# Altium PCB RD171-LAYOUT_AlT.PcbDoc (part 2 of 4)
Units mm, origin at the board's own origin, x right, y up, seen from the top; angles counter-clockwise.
Board outline 318.5 x 127 mm, 6 copper layers (TOP, Mid-Layer 1, Mid-Layer 2, Mid-Layer 3, Mid-Layer 4, BOTTOM), stack 1.422 mm thick; 473 components, 225 nets, 1188 pads, 1192 vias.
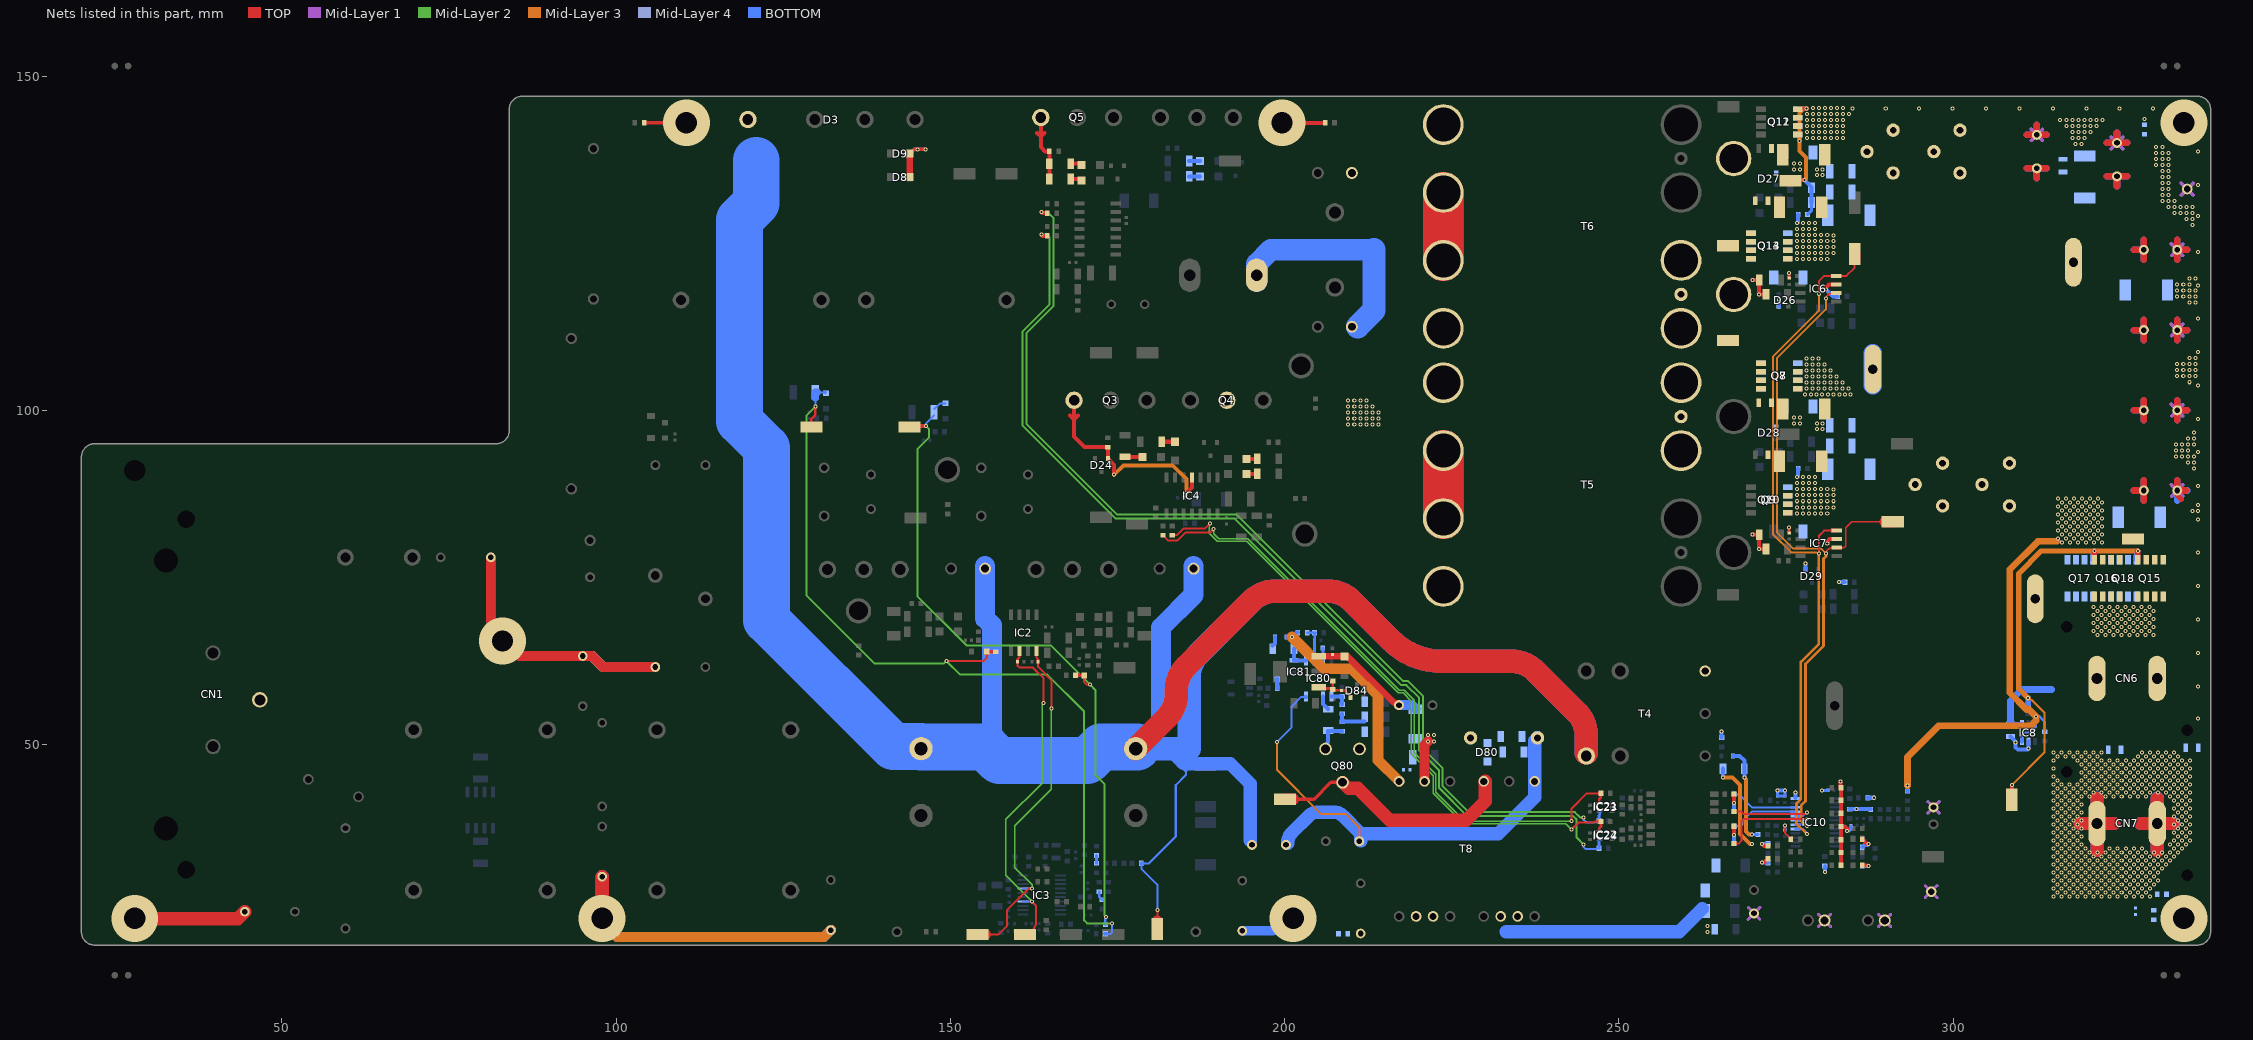
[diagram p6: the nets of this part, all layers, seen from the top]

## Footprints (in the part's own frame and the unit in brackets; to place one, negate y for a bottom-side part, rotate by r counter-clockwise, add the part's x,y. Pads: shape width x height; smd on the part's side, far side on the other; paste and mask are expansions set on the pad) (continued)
T_I_AN0545_GS [mm] "KC00080BKP"
  round 6.1 hole 5.1 paste-6.2 mask+0: 1(-17.78,15.24) 3(-17.78,5.08) 4(-17.78,-5.08) 6(-17.78,-15.24) 7(17.78,-15.24) 9(17.78,-5.08) 10(17.78,5.08) 12(17.78,15.24)
  round 2 hole 1 paste-2.1 mask+0: 8(17.78,-10.16) 11(17.78,10.16)
  round 5.3 hole 4.3 paste-5.4 mask+0: 13(25.65,-10.16) 14(25.65,10.16)
  silkscreen extent -19.5,-17.5 19.5,17.5
T_I_P009-203_PO [mm] "KC00080BKP"
  round 1.6 hole 1 paste-1.7 mask+0: 1(-3.6,-3.5) 2(3.6,-3.5)
  round 1.5 hole 0.9 paste-1.6 mask+0: 3(2.575,3.5) 4(-2.575,3.5)
  silkscreen extent -6,-5.2 6,6.8
T_I_PE-63587NL_PU [mm] "KC00080BKP"
  round 2.6 hole 1.6 paste-2.7 mask+0: 1(-8.89,6.35) 2(-8.89,-6.35) 6(-3.81,6.35) 7(-3.81,-6.35)
  round 1.7 hole 1.1 paste-1.8 mask+0: 3(8.89,6.35) 4(8.89,0) 5(8.89,-6.35)
  silkscreen extent -11.43,-8.89 11.43,8.89
T_I_WT2020_GS [mm] "KC00080BKP"
  round 1.6 hole 1.05 paste-1.7 mask+0: 1(-10.1,10.14) 2(-10.1,6.33) 3(-10.1,2.52) 4(-10.1,-2.52) 5(-10.1,-6.33) 6(-10.1,-10.14) 7(10.1,-10.14) 8(10.1,-7.6) 9(10.1,-5.06) 10(10.1,-2.52) 11(10.1,2.52) 12(10.1,5.06) 13(10.1,7.6) 14(10.1,10.14)
  silkscreen extent -11.6,-11.6 11.6,11.6
TM_I_AC-P05CP24_ED [mm] "KC00080BKP"
  round 2.3 hole 1.65 paste-2.4 mask+0: 1(6.2,-15.8) 2(-0.8,-22.8) 3(-7.8,-15.8)
  round 0 hole 2.6 slot 5.8 at 90 deg unplated paste-5.8 mask+0: ""(-26.2,-11.8) ""(26.2,-11.8)
  round 0 hole 3.6 unplated paste-3.6 mask+0: ""(-20.05,-8.75) ""(20.05,-8.75)
  silkscreen extent -27.5,-23.8 27.5,2.9
TM_I_OP-910_GS [mm] "KC00080BKP"
  oval 6.8x2.6 / inner round 0 / far side oval 6.8x2.6 hole 1.6 slot 5.8 at 0 deg paste-7 mask+0: 1(0,4.5) 2(0,-4.5)
  round 0 hole 1.7 unplated paste-1.7 mask+0: ""(-7.75,-9) ""(7.75,9)
  silkscreen extent -9.5,-10.5 9.5,10.5
TP_I_LC-22_GS [mm] "KC00080BKP"
  round 1.6 hole 1 paste-1.7 mask+0: 1(0,0)
  silkscreen extent -1.65,-1.65 1.65,1.65
TP_I_TH2.8_TBLC3.8_ILC0_RC3.9_GS [mm] "KC00080BKP"
  round 3.8 / inner round 0 / far side round 3.8 hole 2.8 paste-3.9 mask+0: 1(0,0)
  silkscreen extent -2.15,-2.15 2.12,2.15
TP_S_HK-2_M8 [mm] "KC00080BKP"
  rect 3.3x1.7 smd paste-3.4 mask+0: 1(0,0)
  silkscreen extent -2,-1.2 2,1.2
TR_I_TO220SIS_TS_1 [mm] "KC00080BKP"
  round 1.9 hole 1.3 paste-2 mask+0: D(0,-5) G(-2.54,0) S(2.54,0)
  silkscreen extent -5,-3.84 5,2.92
TR_I_TO247_3_TS [mm] "KC00080BKP"
  round 2.6 hole 1.6 paste-2.7 mask+0: D(0,0) G(-5.44,0) S(5.44,0)
  silkscreen extent -7.97,-2.29 7.97,2.73
TR_S_SOP-ADVANCE_TS#1 [mm] "KC00080BKP"
  rect 0.85x1.45 smd paste-1.55 mask+0: 1(-1.905,-2.75) 2(-0.635,-2.75) 3(0.635,-2.75) 4(1.905,-2.75) 5(1.905,2.75) 6(0.635,2.75) 7(-0.635,2.75) 8(-1.905,2.75)
  silkscreen extent -2.58,-2.5 2.57,2.5
TR_S_SOP-ADVANCE_TS#2 [mm] "KC00080BKP"
  rect 0.85x1.45 smd paste-1.55 mask+0: 1(1.905,2.75) 2(0.635,2.75) 3(-0.635,2.75) 4(-1.905,2.75) 5(-1.905,-2.75) 6(-0.635,-2.75) 7(0.635,-2.75) 8(1.905,-2.75)
  silkscreen extent -2.58,-2.5 2.57,2.5
ZD_I_TND14V-561_CC [mm] "KC00080BKP"
  round 1.6 hole 1.05 paste-1.7 mask+0: 1(3.75,-1.3) 2(-3.75,1.3)
  silkscreen extent -8,-3.35 8,3.35

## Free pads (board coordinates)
  round 0 hole 3.2 unplated paste-3.2 mask+0: ""(28,91)
  round 0 hole 2 unplated paste-2 mask+0: ""(32.25,15.5) ""(32.25,151.5) ""(326.25,15.5) ""(326.25,151.5)

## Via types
v1: diameter 0.6, hole 0.3, TOP to BOTTOM, 1184 vias
v2: diameter 7, hole 3.2, TOP to BOTTOM, 8 vias

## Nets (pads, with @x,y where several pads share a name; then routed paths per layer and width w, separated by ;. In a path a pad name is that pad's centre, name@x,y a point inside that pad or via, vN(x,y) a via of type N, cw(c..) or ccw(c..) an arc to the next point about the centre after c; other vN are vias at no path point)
$BN000001: R90.2 R227.1 | length 1.2
  BOTTOM w0.4: R227.1@171.85,32.25 R90.2@171.85,33.4
$BN000002: R2.2 R228.1 | length 1.4
  BOTTOM w0.4: R228.1@172.25,28 172.25,27.25 R2.2@172.7,26.8
ADJ: C805.1 D84.A IC81.ADJ R810.2 R811.1 | length 6.9
  TOP w0.4: IC81.ADJ@205.1,58.6 205.3,58.4 207,58.4 R811.1@207.2,58.2 ; R810.2@207.2,59.5 R811.1@207.2,58.2 ; C805.1@208.5,58.125 207.275,58.125 R811.1@207.2,58.2 ; C805.1@208.5,58.15 208.5,58.1 209.05,58.1 209.85,57.3 D84.A@209.85,57.05
AUX: C810.2 D81.A R808.2 T8.6 | length 32.6
  Mid-Layer 3 w1.6: v1(201.1,66.1) 205.85,61.35 210,61.35 213.95,57.4 213.95,47.66 T8.6@217.11,44.5
  BOTTOM w0.6: D81.A@200.25,66.1 v1(201.1,66.1) 201.75,66.75 R808.2@201.95,66.75
CONN002: C19.1 D24.A IC4.11 Q3.S Q4.D R31.1 T5.1 T6.1 | length 35.1
  TOP w0.6: 167.9,99.2 168.5,98.6 ; Q3.S@168.5,101.5 168.5,98.6 ; 169.1,99.2 168.5,98.6 ; v1(174.5,90.4) 174.5,91.85 D24.A@173.55,92.8 R31.1@173.55,94.5 170.05,94.5 168.5,96.05 168.5,98.6 ; v1(185.3,87.65) 186.1,88.45 IC4.11@186.1,89.9
  Mid-Layer 3 w0.6: v1(174.5,90.4) 175.85,91.75 183.25,91.75 185.3,89.7 v1(185.3,87.65)
  BOTTOM w0.45: C19.1@184.925,86.9 185.3,87.275 v1(185.3,87.65)
CONN003: D18.C D19.A L3.2 T5.6 T6.6 | length 33.7
  BOTTOM w3.2: L3.2@195.8,119.3 L3.2@195.8,120.2 195.8,121.9 197.9,124 213.35,124
  BOTTOM w3.5: D19.A@210.9,112.5 213.35,114.95 213.35,124 213.25,123.9
  other v1: 209.5,97.9 210.4,97.9 211.3,97.9 212.2,97.9 213.1,97.9 214,97.9 209.5,98.8 210.4,98.8 211.3,98.8 212.2,98.8 213.1,98.8 214,98.8 209.5,99.7 210.4,99.7 211.3,99.7 212.2,99.7 213.1,99.7 214,99.7 209.5,100.6 210.4,100.6 211.3,100.6 212.2,100.6 213.1,100.6 209.5,101.5 210.4,101.5 211.3,101.5 212.2,101.5
CONN004: C2.2 C3.2 C4.2 C5.2 C8.2 C9.2 C59.2 C102.2 IC8.3 IC8.6 L5.2 L6.2 Q15.1 Q15.2 Q15.3 Q16.1 Q16.2 Q16.3 Q17.1 Q17.2 Q17.3 Q18.1 Q18.2 Q18.3 R75.2 R77.1 R78.1 R106.1 R107.2 R128.2 R129.1 R199.2 R200.2 R201.2 TP31.1 | length 123.1
  TOP w1: 311,136.2 C8.2@312.5,136.2 ; 312.5,134.7 C8.2@312.5,136.2 ; 314,136.2 C8.2@312.5,136.2 ; 323,135 C9.2@324.5,135 ; 324.5,133.5 C9.2@324.5,135 ; 326,135 C9.2@324.5,135 ; 327,88 C5.2@328.5,88 ; 327,100 C4.2@328.5,100 ; 327,112 C3.2@328.5,112 ; 327,124 C2.2@328.5,124 ; 328.5,86.5 C5.2@328.5,88 ; 328.5,89.5 C5.2@328.5,88 ; 328.5,98.5 C4.2@328.5,100 ; 328.5,101.5 C4.2@328.5,100 ; 328.5,110.5 C3.2@328.5,112 ; 328.5,113.5 C3.2@328.5,112 ; 328.5,122.5 C2.2@328.5,124 ; 328.5,125.5 C2.2@328.5,124
  Mid-Layer 1 w0.3: v1(315.65,80.8) v1(316.25,80.2)
  Mid-Layer 3 w1: v1(293.15,43.85) 293.15,48.15 297.8,52.8 311.6,52.8 312.4,53.6 v1(312.4,54.2) 311.35,55.25 310.95,55.25 308.45,57.75 308.45,76.2 312.65,80.4 315.52,80.4
  BOTTOM w0.3: IC8.3@310.3,50.95 310.3,51.4 310.7,51.8 311.8,51.8 312.2,52.2 IC8.6@312.2,52.85
  BOTTOM w0.4: v1(312.4,54.2) 312.9,54.2 313.7,53.4 C59.2@313.7,51.9
  BOTTOM w0.6: R75.2@293.15,43 v1(293.15,43.85) ; IC8.3@310.3,50.5 IC8.3@310.3,50.95 ; IC8.6@312.2,52.85 IC8.6@312.2,53.1 312.2,53.75 312.4,53.95 v1(312.4,54.2)
  BOTTOM w1: 311,136.2 C8.2@312.5,136.2 ; 312.5,134.7 C8.2@312.5,136.2 ; 314,136.2 C8.2@312.5,136.2 ; 323,135 C9.2@324.5,135 ; 324.5,133.5 C9.2@324.5,135 ; 326,135 C9.2@324.5,135 ; 327,88 C5.2@328.5,88 ; 327,100 C4.2@328.5,100 ; 327,112 C3.2@328.5,112 ; 327,124 C2.2@328.5,124 ; 328.5,86.5 C5.2@328.5,88 ; 328.5,89.5 C5.2@328.5,88 ; 328.5,98.5 C4.2@328.5,100 ; 328.5,101.5 C4.2@328.5,100 ; 328.5,110.5 C3.2@328.5,112 ; 328.5,113.5 C3.2@328.5,112 ; 328.5,122.5 C2.2@328.5,124 ; 328.5,125.5 C2.2@328.5,124
  other v1: 317.45,80.2 318.65,80.2 319.85,80.2 321.05,80.2 322.25,80.2 316.85,80.8 318.05,80.8 319.25,80.8 320.45,80.8 321.65,80.8 316.25,81.4 317.45,81.4 318.65,81.4 319.85,81.4 321.05,81.4 322.25,81.4 315.65,82 316.85,82 318.05,82 319.25,82 320.45,82 321.65,82 316.25,82.6 317.45,82.6 318.65,82.6 319.85,82.6 321.05,82.6 322.25,82.6 315.65,83.2 316.85,83.2 318.05,83.2 319.25,83.2 320.45,83.2 321.65,83.2 316.25,83.8 317.45,83.8 318.65,83.8 319.85,83.8 321.05,83.8 322.25,83.8 315.65,84.4 316.85,84.4 318.05,84.4 319.25,84.4 320.45,84.4 321.65,84.4 316.25,85 317.45,85 318.65,85 319.85,85 321.05,85 322.25,85 315.65,85.6 316.85,85.6 318.05,85.6 319.25,85.6 320.45,85.6 321.65,85.6 316.25,86.2 317.45,86.2 318.65,86.2 319.85,86.2 321.05,86.2 322.25,86.2 315.65,86.8 316.85,86.8 318.05,86.8 319.25,86.8 320.45,86.8 321.65,86.8
CS: D14.C R67.2 R185.2 | length 14.7
  Mid-Layer 3 w0.6: v1(268.75,45.05) 269,44.8 269,37 269.45,36.55 v1(269.9,36.55)
  BOTTOM w0.4: v1(269.9,36.55) R67.2@270.8,36.55
  BOTTOM w0.6: D14.C@267.05,48.3 268.05,48.3 268.75,47.6 R185.2@268.75,46.4 v1(268.75,45.05)
CSA: D13.C D33.C R7.2 R87.1 R170.1 TP2.1 | length 131.4
  TOP w0.3: v1(149.4,62.5) 155,62.5 155.45,62.95 D33.C@155.45,63.667
  TOP w0.4: TP2.1@129.2,97.5 129.2,98.7 129.8,99.3 v1(129.8,100.55)
  TOP w0.5: D33.C@155.4,63.9 R87.1@156.7,63.9
  TOP w0.8: D33.C@155.45,63.667 D33.C@155.45,63.9
  Mid-Layer 2 w0.3: v1(129.8,100.55) 128.45,99.2 128.45,72.333 138.683,62.1 149,62.1 v1(149.4,62.5) 151.45,60.45 164.499,60.45 170,54.949 170,23.7 170.45,23.25 v1(174.2,23.25)
  BOTTOM w0.3: v1(129.8,100.55) R7.2@129.8,101.867 ; R7.2@130.053,102.7 D13.C@131.136,102.7 ; R170.1@173.337,21.7 173.95,21.7 174.2,21.95 v1(174.2,23.25)
  BOTTOM w0.5: D13.C@131.136,102.7 D13.C@131.3,102.7
  BOTTOM w0.58: R170.1@173.14,21.7 R170.1@173.337,21.7
  BOTTOM w1.1: R7.2@129.8,101.867 R7.2@129.8,102.7 R7.2@130.053,102.7
CSB: D12.C D31.C R8.2 R83.1 R169.1 TP1.1 | length 103.6
  TOP w0.3: D31.C@170,60.35 170,59.35 170.35,59 v1(170.85,59)
  TOP w0.5: R83.1@168.7,60.35 D31.C@170,60.35
  TOP w0.6: TP1.1@144.7,97.65 v1(146.35,97.65)
  Mid-Layer 2 w0.3: v1(146.35,97.65) 146.8,97.2 146.8,95.95 145.05,94.2 145.05,72.2 152.4,64.85 165,64.85 v1(170.85,59) 171.7,58.15 171.7,45.449 173.05,44.099 173.05,24.45 v1(173.3,24.2)
  BOTTOM w0.3: v1(146.35,97.65) 146.35,98.05 R8.2@147.55,99.25 ; R8.2@147.6,100.2 148.45,101.05 D12.C@149.25,101.05
  BOTTOM w0.4: R169.1@173.175,23.075 173.175,23.85 v1(173.3,24.2)
FG1: CN1.2
FG2: C79.1 | length 13.4
  TOP w2: 31.5,23.95 43.4,23.95 C79.1@44.45,25
  other v2: 28,24
FG3: C32.1 C64.1 C78.1 | length 84.1
  TOP w1.45: v2@81.25,68.5 C78.1@81.25,78 ; v2@85.5,63.25 C32.1@95,63.25 96.375,63.25 ; 96.4,63.25 96.375,63.25 ; C64.1@105.85,61.6 98.025,61.6 96.375,63.25
  Mid-Layer 3 w1.45: C32.1@95,63.25 96.375,63.25 98.025,61.6 C64.1@105.85,61.6
  Mid-Layer 4 w1.45: C32.1@95,63.25 96.375,63.25 98.025,61.6 C64.1@105.85,61.6
  BOTTOM w1.45: v2@81.25,68.5 C78.1@81.25,78 ; v2@85.5,63.25 C32.1@95,63.25 96.375,63.25 ; 96.4,63.25 98.05,61.6 C64.1@105.85,61.6
  other v2: 83,65.5
FG4: C31.1 C63.1 | length 109.7
  TOP w2: v2(97.9,24) C31.1@97.9,30.25
  Mid-Layer 3 w1.5: 100.1,21.25 131.1,21.25 C63.1@132.1,22.25
  Mid-Layer 4 w1.5: 100.1,21.25 131.1,21.25 C63.1@132.1,22.25
  BOTTOM w1.5: 100.1,21.25 131.1,21.25 C63.1@132.1,22.25
  BOTTOM w2: v2(97.9,24) C31.1@97.9,30.25
FG5: C101.2 R805.2 | length 4.6
  BOTTOM w1.45: C101.2@193.65,22.15 198.25,22.15
  other v2: 201.25,24
FG6: C93.1 C94.2 R205.1 R206.1
  other v2: 334.5,24
FG7: R204.1
  other v2: 334.5,143
GDA: C81.2 IC2.2 IC3.14 TP5.1 | length 51.6
  TOP w0.3: C81.2@159.95,62.4 159.95,62.675 160.1,62.825 ; C81.2@160.025,62.225 160.025,61.825 160.35,61.5 162.35,61.5 163.95,59.9 v1(163.95,56.2) ; C81.2@160.025,62.4 160.1,62.4 160.1,62.825 ; IC2.2@160.315,64 160.315,63.04 160.1,62.825 ; TP5.1@162,21.6 162.8,23.123 162.8,25.925 v1(162.2,26.525)
  TOP w0.45: C81.2@160.025,62.225 C81.2@160.025,62.4
  Mid-Layer 2 w0.2: v1(162.2,26.525) 158.25,30.475 158.25,38.8 163.7,44.25 163.7,55.95 v1(163.95,56.2)
  BOTTOM w0.3: IC3.14@160.85,26.525 v1(162.2,26.525)
GDB: C80.2 IC2.4 IC3.17 TP6.1 | length 53.9
  TOP w0.3: TP6.1@155.233,21.6 157.2,21.6 158.45,22.85 158.45,25.2 161.75,28.5 v1(162.2,28.5) ; IC2.4@162.855,64 162.855,63.045 163.05,62.85 ; C80.2@163.125,62.225 163.125,61.625 165.1,59.65 v1(165.1,55.4) ; C80.2@163.125,62.4 163.05,62.4 163.05,62.85 ; C80.2@163.2,62.5 163.2,62.7 163.05,62.85
  TOP w0.45: C80.2@163.125,62.225 C80.2@163.125,62.4
  TOP w1.7: TP6.1@154.05,21.6 TP6.1@155.233,21.6
  Mid-Layer 2 w0.2: v1(162.2,28.5) 162.2,29.05 159.65,31.6 159.65,37.886 165.1,43.336 v1(165.1,55.4)
  BOTTOM w0.3: IC3.17@160.85,28.475 161.8,28.475 v1(162.2,28.5)
HS1_1: R224.2 | length 6.4
  TOP w0.6: v2(199.6,143) R224.2@206.05,143
HS1_2: R225.2 | length 6.3
  TOP w0.5: R225.2@104.2,143 v2(110.5,143)
IN: C804.2 C808.1 D82.C D83.C IC81.IN | length 17.9
  TOP w0.3: 207.15,63.2 C808.1@207.15,63.45
  TOP w0.95: IC81.IN@205.1,63.2 207.15,63.2 D83.C@208.95,63.2
  TOP w1: D83.C@208.9,63.2 209.4,63.2 216.236,56.364 C804.2@217.1,55.9
  BOTTOM w1.5: C804.2@217.1,55.9 219,55.9 D82.C@219.55,55.35
LGND: C2.1 C3.1 C4.1 C5.1 C8.1 C9.1 C23.1 C24.1 C25.1 C26.1 C27.1 C51.1 C60.1 C61.1 C68.1 C69.1 C88.1 C89.1 C90.1 C91.1 C92.1 C94.1 C99.1 C100.1 C102.1 C809.1 C811.1 CN7.1 CN7.2 CN8.2 CN9.2 CN10.2 D26.A D27.A D28.A D29.A IC6.3 IC7.3 IC8.2 IC10.24 Q7.1 Q7.2 Q7.3 Q8.1 Q8.2 Q8.3 Q9.1 Q9.2 Q9.3 Q10.1 Q10.2 Q10.3 Q11.1 Q11.2 Q11.3 Q12.1 Q12.2 Q12.3 Q13.1 Q13.2 Q13.3 Q14.1 Q14.2 Q14.3 R9.1 R19.1 R21.1 R22.1 R25.1 R43.1 R45.1 R48.1 R50.1 R51.1 R52.1 R53.1 R54.1 R55.1 R56.1 R61.1 R64.1 R66.1 R70.1 R76.1 R105.1 R118.1 R119.1 R140.1 R141.1 R180.1 R181.1 R182.1 R184.1 R185.1 R194.2 R195.2 R196.2 R197.2 R199.1 R200.1 R201.1 R204.2 R205.2 R206.2 R208.1 R209.1 R805.1 R820.1 T4.3 T8.8 T8.9 TP41.1 TP42.1 | length 306.5
  TOP w0.3: v1@274.8,37.95 v1(274.8,37.9) 274.8,36.81 R70.1@275.76,35.85
  TOP w0.45: C60.1@275.45,81.7 v1(275.45,82.45) ; C61.1@275.45,119.8 v1(275.45,120.55)
  TOP w0.6: v1(267.2,36.5) R197.2@267.2,37.8 ; v1(267.2,41.3) R196.2@267.2,42.6 ; v1(269.95,81.4) C91.1@270.95,81.4 ; v1(269.95,119.5) C88.1@270.95,119.5 ; C91.1@270.95,81.35 v1(270.95,79.25) C90.1@272,79.25 ; C88.1@270.95,119.45 v1(270.95,117.35) C89.1@272,117.35 ; v1(271.4,32.35) 271.7,32.35 R208.1@272.3,32.95 ; v1(271.4,35.15) 271.7,34.85 R209.1@272.25,34.85 ; v1(280.95,118.1) 280.95,118.385 281.4,118.835 IC6.3@282.5,118.835 ; v1(281.15,80.05) 281.15,80.4 281.485,80.735 IC7.3@282.5,80.735 ; R50.1@283.15,43.55 v1(283.15,44.5) ; R182.1@283.2,31.95 R53.1@283.2,33.85 R51.1@283.2,35.75 R180.1@283.2,37.7 ; R50.1@283.2,43.55 R181.1@283.2,41.65 R52.1@283.2,39.75 R180.1@283.2,37.75 R180.1@283.2,37.7 ; v1(284.1,37.05) 284.1,37.45 283.85,37.7 R180.1@283.2,37.7 ; R184.1@286.4,31.95 287.2,31.95 v1(287.3,31.85) ; R55.1@286.4,35.85 287.1,35.15 v1(287.35,35.15)
  TOP w0.8: C5.1@333.5,88 333.5,87.265 334.115,86.65
  TOP w1: 311,141.2 C8.1@312.5,141.2 ; 312.5,142.7 C8.1@312.5,141.2 ; 314,141.2 C8.1@312.5,141.2 ; 323,140 C9.1@324.5,140 ; 324.5,141.5 C9.1@324.5,140 ; 326,140 C9.1@324.5,140 ; 333.5,89.5 C5.1@333.5,88 334.85,88 ; 333.5,98.5 C4.1@333.5,100 ; 333.5,101.5 C4.1@333.5,100 ; 333.5,110.5 C3.1@333.5,112 ; 333.5,113.5 C3.1@333.5,112 ; 333.5,122.5 C2.1@333.5,124 ; 333.5,125.5 C2.1@333.5,124 ; 335,100 C4.1@333.5,100 ; 335,112 C3.1@333.5,112 ; 335,124 C2.1@333.5,124
  TOP w2: 319,38.2 CN7.1@321.5,38.2 ; 321.5,34.2 CN7.1@321.5,38.2 ; 321.5,41.9 CN7.1@321.5,38.2 ; 324,38.2 CN7.1@321.5,38.2 ; 328,38.2 CN7.2@330.5,38.2 ; 330.5,34.1 CN7.2@330.5,38.2 ; 330.5,41.9 CN7.2@330.5,38.2 ; v1@332.8,38.2 CN7.2@330.5,38.2
  Mid-Layer 1 w0.4: 269.35,23.9 C809.1@270.2,24.75 ; 269.35,25.6 C809.1@270.2,24.75 ; 271.05,23.9 C809.1@270.2,24.75 ; 271.1,25.65 C809.1@270.2,24.75 ; 279.85,22.8 CN8.2@280.75,23.7 ; 279.85,24.6 CN8.2@280.75,23.7 ; 281.65,22.8 CN8.2@280.75,23.7 ; 281.65,24.6 CN8.2@280.75,23.7 ; 288.85,22.8 CN9.2@289.75,23.7 ; 288.85,24.6 CN9.2@289.75,23.7 ; 290.65,22.8 CN9.2@289.75,23.7 ; 290.65,24.6 CN9.2@289.75,23.7 ; 295.8,27.1 TP42.1@296.7,28 ; 295.8,28.9 TP42.1@296.7,28 ; 296.2,39.77 CN10.2@297.05,40.62 ; 296.2,41.47 CN10.2@297.05,40.62 ; 297.6,27.1 TP42.1@296.7,28 ; 297.6,28.9 TP42.1@296.7,28 ; 297.9,39.77 CN10.2@297.05,40.62 ; 297.9,41.47 CN10.2@297.05,40.62
  Mid-Layer 1 w0.5: 311.65,140.35 C8.1@312.5,141.2 ; 311.65,142.05 C8.1@312.5,141.2 ; 313.35,140.35 C8.1@312.5,141.2 ; 313.35,142.05 C8.1@312.5,141.2 ; 323.65,139.15 C9.1@324.5,140 ; 323.65,140.85 C9.1@324.5,140 ; 325.35,139.15 C9.1@324.5,140 ; 325.35,140.85 C9.1@324.5,140 ; 332.6,88.9 C5.1@333.5,88 ; 332.6,100.9 C4.1@333.5,100 ; 332.6,112.9 C3.1@333.5,112 ; 332.6,124.9 C2.1@333.5,124 ; 332.65,87.15 C5.1@333.5,88 ; 332.65,99.15 C4.1@333.5,100 ; 332.65,111.15 C3.1@333.5,112 ; 332.65,123.15 C2.1@333.5,124 ; 334.1,132.2 TP41.1@335,133.1 ; 334.1,134 TP41.1@335,133.1 ; 334.35,87.15 C5.1@333.5,88 ; 334.35,88.85 C5.1@333.5,88 ; 334.35,99.15 C4.1@333.5,100 ; 334.35,100.85 C4.1@333.5,100 ; 334.35,111.15 C3.1@333.5,112 ; 334.35,112.85 C3.1@333.5,112 ; 334.35,123.15 C2.1@333.5,124 ; 334.35,124.85 C2.1@333.5,124 ; 335.9,132.2 TP41.1@335,133.1 ; 335.9,134 TP41.1@335,133.1
  Mid-Layer 3 w0.6: v1(265.55,45.05) 267,45.05 268.1,43.95 268.1,36.65 269.6,35.15 v1(269.9,35.15)
  Mid-Layer 4 w0.4: 269.3,23.85 C809.1@270.2,24.75 ; 269.35,25.6 C809.1@270.2,24.75 ; 271.05,23.9 C809.1@270.2,24.75 ; 271.05,25.6 C809.1@270.2,24.75 ; 279.85,22.8 CN8.2@280.75,23.7 ; 279.85,24.6 CN8.2@280.75,23.7 ; 281.65,22.8 CN8.2@280.75,23.7 ; 281.65,24.6 CN8.2@280.75,23.7 ; 288.85,22.8 CN9.2@289.75,23.7 ; 288.85,24.6 CN9.2@289.75,23.7 ; 290.65,22.8 CN9.2@289.75,23.7 ; 290.65,24.6 CN9.2@289.75,23.7 ; 295.8,27.1 TP42.1@296.7,28 ; 295.8,28.9 TP42.1@296.7,28 ; 296.2,39.77 CN10.2@297.05,40.62 ; 296.2,41.47 CN10.2@297.05,40.62 ; 297.6,27.1 TP42.1@296.7,28 ; 297.6,28.9 TP42.1@296.7,28 ; 297.9,39.77 CN10.2@297.05,40.62 ; 297.93,41.5 CN10.2@297.05,40.62
  Mid-Layer 4 w0.5: 311.65,140.35 C8.1@312.5,141.2 ; 311.65,142.05 C8.1@312.5,141.2 ; 313.35,140.35 C8.1@312.5,141.2 ; 313.35,142.05 C8.1@312.5,141.2 ; 323.65,139.15 C9.1@324.5,140 ; 323.65,140.85 C9.1@324.5,140 ; 325.35,139.15 C9.1@324.5,140 ; 325.35,140.85 C9.1@324.5,140 ; 332.6,88.9 C5.1@333.5,88 ; 332.6,100.9 C4.1@333.5,100 ; 332.6,112.9 C3.1@333.5,112 ; 332.6,124.9 C2.1@333.5,124 ; 332.65,87.15 C5.1@333.5,88 ; 332.65,99.15 C4.1@333.5,100 ; 332.65,111.15 C3.1@333.5,112 ; 332.65,123.15 C2.1@333.5,124 ; 334.1,132.2 TP41.1@335,133.1 ; 334.1,134 TP41.1@335,133.1 ; 334.35,87.15 C5.1@333.5,88 ; 334.35,88.85 C5.1@333.5,88 ; 334.35,99.15 C4.1@333.5,100 ; 334.35,100.85 C4.1@333.5,100 ; 334.35,111.15 C3.1@333.5,112 ; 334.35,112.85 C3.1@333.5,112 ; 334.35,123.15 C2.1@333.5,124 ; 334.35,124.85 C2.1@333.5,124 ; 335.9,132.2 TP41.1@335,133.1 ; 335.9,134 TP41.1@335,133.1
  BOTTOM w0.45: v1(273.7,43.1) C23.1@273.7,42.325 C24.1@274.8,42.325 v1(274.8,43.1) ; C26.1@274.8,37.225 v1(274.8,37.9) ; v1(280.35,43.15) C99.1@281.225,43.15 ; v1(284.1,37.05) 284.15,37.1 284.45,37.1 284.675,37.325 C25.1@284.675,37.85
  BOTTOM w0.6: R9.1@265.35,51.05 v1(265.35,51.95) ; v1(265.55,45.05) R185.1@265.55,46.4 ; R195.2@267.2,35.2 v1(267.2,36.5) ; R194.2@267.2,40 v1(267.2,41.3) ; v1(271.4,32.35) R64.1@272.3,32.35 ; v1(271.4,35.15) R66.1@272.3,35.15 ; v1(273.7,43.1) v1(274.8,43.1) ; D26.A@273.9,115.5 v1(273.9,116.55) ; IC10.24@276.4,42.05 v1(276.4,42.85) ; v1@276.8,90.1 R22.1@276.8,91.3 ; v1@276.8,128.1 R19.1@276.8,129.3 ; D29.A@277.9,76.2 v1(277.9,77.1) ; v1(280.8,30.95) R54.1@280.8,31.8 ; v1(280.95,118.1) 282,117.05 R21.1@282.7,117.05 ; v1(282.9,74.3) R25.1@283.75,74.3 ; R48.1@284.5,40.35 v1(285.5,40.35) R43.1@287.65,40.35 ; R56.1@286.4,34.65 286.7,34.95 287.15,34.95 v1(287.35,35.15) ; R61.1@286.45,31.85 v1(287.3,31.85) ; R45.1@287.2,42.05 v1(288.15,42.05) ; C100.1@308.55,51.2 309.3,50.45 v1(309.3,50.3) 309.3,49.6 309.65,49.25 311.1,49.25 v1(311.25,49.4) IC8.2@311.25,50.5
  BOTTOM w1: 311,141.2 C8.1@312.5,141.2 ; 312.5,142.7 C8.1@312.5,141.2 ; 314,141.2 C8.1@312.5,141.2 ; 323,140 C9.1@324.5,140 ; 324.5,141.5 C9.1@324.5,140 ; 326,140 C9.1@324.5,140 ; 333.5,86.5 C5.1@333.5,88 ; 333.5,89.5 C5.1@333.5,88 ; 333.5,98.5 C4.1@333.5,100 ; 333.5,101.5 C4.1@333.5,100 ; 333.5,110.5 C3.1@333.5,112 ; 333.5,113.5 C3.1@333.5,112 ; 333.5,122.5 C2.1@333.5,124 ; 333.5,125.5 C2.1@333.5,124 ; 335,88 C5.1@333.5,88 ; 335,100 C4.1@333.5,100 ; 335,112 C3.1@333.5,112 ; 335,124 C2.1@333.5,124
  BOTTOM w2: 319,38.2 CN7.1@321.5,38.2 ; 321.5,34.2 CN7.1@321.5,38.2 ; 321.5,42 CN7.1@321.5,38.2 ; 324,38.2 CN7.1@321.5,38.2 ; 328,38.2 CN7.2@330.5,38.2 ; 330.5,34.2 CN7.2@330.5,38.2 ; 330.5,42 CN7.2@330.5,38.2 ; v1@333,38.2 CN7.2@330.5,38.2
  other v1: 263.25,21.95 263.25,22.85 315,27.25 316.2,27.25 317.4,27.25 318.6,27.25 319.8,27.25 321,27.25 322.2,27.25 323.4,27.25 324.6,27.25 325.8,27.25 327,27.25 328.2,27.25 329.4,27.25 315.6,27.85 316.8,27.85 318,27.85 319.2,27.85 320.4,27.85 321.6,27.85 322.8,27.85 324,27.85 325.2,27.85 326.4,27.85 327.6,27.85 328.8,27.85 315,28.45 316.2,28.45 317.4,28.45 318.6,28.45 319.8,28.45 321,28.45 322.2,28.45 323.4,28.45 324.6,28.45 325.8,28.45 327,28.45 328.2,28.45 329.4,28.45 315.6,29.05 316.8,29.05 318,29.05 319.2,29.05 320.4,29.05 321.6,29.05 322.8,29.05 324,29.05 325.2,29.05 326.4,29.05 327.6,29.05 328.8,29.05 330,29.05 315,29.65 316.2,29.65 317.4,29.65 318.6,29.65 319.8,29.65 321,29.65 322.2,29.65 323.4,29.65 324.6,29.65 325.8,29.65 327,29.65 328.2,29.65 329.4,29.65 330.6,29.65 315.6,30.25 316.8,30.25 318,30.25 319.2,30.25 320.4,30.25 321.6,30.25 322.8,30.25 324,30.25 325.2,30.25 326.4,30.25 327.6,30.25 328.8,30.25 330,30.25 315,30.85 316.2,30.85 317.4,30.85 318.6,30.85 319.8,30.85 321,30.85 322.2,30.85 323.4,30.85 324.6,30.85 325.8,30.85 327,30.85 328.2,30.85 329.4,30.85 330.6,30.85 315.6,31.45 316.8,31.45 318,31.45 319.2,31.45 320.4,31.45 321.6,31.45 322.8,31.45 324,31.45 325.2,31.45 326.4,31.45 327.6,31.45 328.8,31.45 330,31.45 331.2,31.45 315,32.05 316.2,32.05 317.4,32.05 318.6,32.05 319.8,32.05 321,32.05 322.2,32.05 323.4,32.05 324.6,32.05 325.8,32.05 327,32.05 328.2,32.05 329.4,32.05 330.6,32.05 331.8,32.05 315.6,32.65 316.8,32.65 318,32.65 319.2,32.65 320.4,32.65 321.6,32.65 322.8,32.65 324,32.65 325.2,32.65 326.4,32.65 327.6,32.65 328.8,32.65 330,32.65 331.2,32.65 332.4,32.65 315,33.25 316.2,33.25 317.4,33.25 318.6,33.25 319.8,33.25 321,33.25 322.2,33.25 323.4,33.25 324.6,33.25 325.8,33.25 327,33.25 328.2,33.25 329.4,33.25 330.6,33.25 331.8,33.25 333,33.25 315.6,33.85 316.8,33.85 318,33.85 319.2,33.85 320.4,33.85 321.6,33.85 322.8,33.85 324,33.85 325.2,33.85 326.4,33.85 327.6,33.85 328.8,33.85 330,33.85 331.2,33.85 332.4,33.85 333.6,33.85 315,34.45 316.2,34.45 317.4,34.45 318.6,34.45 319.8,34.45 323.4,34.45 324.6,34.45 325.8,34.45 327,34.45 328.2,34.45 333,34.45 334.2,34.45 315.6,35.05 316.8,35.05 318,35.05 319.2,35.05 332.4,35.05 333.6,35.05 334.8,35.05 315,35.65 316.2,35.65 317.4,35.65 318.6,35.65 333,35.65 334.2,35.65 335.4,35.65 315.6,36.25 316.8,36.25 318,36.25 319.2,36.25 333.6,36.25 334.8,36.25 315,36.85 316.2,36.85 317.4,36.85 318.6,36.85 333,36.85 334.2,36.85 335.4,36.85 315.6,37.45 316.8,37.45 318,37.45 319.2,37.45 333.6,37.45 334.8,37.45 315,38.05 316.2,38.05 317.4,38.05 318.6,38.05 333,38.05 334.2,38.05 335.4,38.05 315.6,38.65 316.8,38.65 318,38.65 319.2,38.65 333.6,38.65 334.8,38.65 315,39.25 316.2,39.25 317.4,39.25 318.6,39.25 333,39.25 334.2,39.25 335.4,39.25 315.6,39.85 316.8,39.85 318,39.85 319.2,39.85 333.6,39.85 334.8,39.85 315,40.45 316.2,40.45 317.4,40.45 318.6,40.45 333,40.45 334.2,40.45 335.4,40.45 315.6,41.05 316.8,41.05 318,41.05 319.2,41.05 333.6,41.05 334.8,41.05 315,41.65 316.2,41.65 317.4,41.65 318.6,41.65 333,41.65 334.2,41.65 335.4,41.65 315.6,42.25 316.8,42.25 318,42.25 319.2,42.25 320.4,42.25 322.8,42.25 324,42.25 325.2,42.25 326.4,42.25 327.6,42.25 328.8,42.25 332.4,42.25 333.6,42.25 334.8,42.25 315,42.85 316.2,42.85 317.4,42.85 318.6,42.85 319.8,42.85 321,42.85 322.2,42.85 323.4,42.85 324.6,42.85 325.8,42.85 327,42.85 328.2,42.85 329.4,42.85 330.6,42.85 331.8,42.85 333,42.85 334.2,42.85 335.4,42.85 315.6,43.45 316.8,43.45 318,43.45 319.2,43.45 320.4,43.45 321.6,43.45 322.8,43.45 324,43.45 325.2,43.45 326.4,43.45 327.6,43.45 328.8,43.45 330,43.45 331.2,43.45 332.4,43.45 333.6,43.45 334.8,43.45 315,44.05 316.2,44.05 317.4,44.05 318.6,44.05 319.8,44.05 321,44.05 322.2,44.05 323.4,44.05 324.6,44.05 325.8,44.05 327,44.05 328.2,44.05 329.4,44.05 330.6,44.05 331.8,44.05 333,44.05 334.2,44.05 335.4,44.05 315.6,44.65 319.2,44.65 320.4,44.65 321.6,44.65 322.8,44.65 324,44.65 325.2,44.65 326.4,44.65 327.6,44.65 328.8,44.65 330,44.65 331.2,44.65 332.4,44.65 333.6,44.65 334.8,44.65 315,45.25 319.8,45.25 321,45.25 322.2,45.25 323.4,45.25 324.6,45.25 325.8,45.25 327,45.25 328.2,45.25 329.4,45.25 330.6,45.25 331.8,45.25 333,45.25 334.2,45.25 335.4,45.25 319.2,45.85 320.4,45.85 321.6,45.85 322.8,45.85 324,45.85 325.2,45.85 326.4,45.85 327.6,45.85 328.8,45.85 330,45.85 331.2,45.85 332.4,45.85 333.6,45.85 334.8,45.85 315,46.45 319.8,46.45 321,46.45 322.2,46.45 323.4,46.45 324.6,46.45 325.8,46.45 327,46.45 328.2,46.45 329.4,46.45 330.6,46.45 331.8,46.45 333,46.45 334.2,46.45 335.4,46.45 319.2,47.05 320.4,47.05 321.6,47.05 322.8,47.05 324,47.05 325.2,47.05 326.4,47.05 327.6,47.05 328.8,47.05 330,47.05 331.2,47.05 332.4,47.05 333.6,47.05 334.8,47.05 315,47.65 318.6,47.65 319.8,47.65 321,47.65 322.2,47.65 323.4,47.65 324.6,47.65 325.8,47.65 327,47.65 328.2,47.65 329.4,47.65 330.6,47.65 331.8,47.65 333,47.65 334.2,47.65 335.4,47.65 315.6,48.25 316.8,48.25 318,48.25 319.2,48.25 320.4,48.25 321.6,48.25 327.6,48.25 328.8,48.25 330,48.25 331.2,48.25 332.4,48.25 333.6,48.25 315,48.85 316.2,48.85 317.4,48.85 318.6,48.85 319.8,48.85 321,48.85 322.2,48.85 328.2,48.85 329.4,48.85 330.6,48.85 331.8,48.85 333,48.85 336.6,53.9 336.6,58.7 336.6,63.7 336.6,68.7 336.6,73.7 336.6,78.7 336.6,83.7 276.65,84.6 277.55,84.6 278.45,84.6 279.35,84.6 280.25,84.6 281.15,84.6 335.75,84.95 336.6,84.95 276.65,85.5 277.55,85.5 278.45,85.5 279.35,85.5 280.25,85.5 281.15,85.5 282.05,85.5 336.6,85.85 276.65,86.4 277.55,86.4 278.45,86.4 279.35,86.4 280.25,86.4 281.15,86.4 282.05,86.4 276.65,87.3 277.55,87.3 278.45,87.3 279.35,87.3 280.25,87.3 281.15,87.3 282.05,87.3 282.05,88.15 276.65,88.2 277.55,88.2 278.45,88.2 279.35,88.2 280.25,88.2 281.15,88.2 336.6,88.7 276.65,89.1 277.55,89.1 278.45,89.1 279.35,89.1 276.65,90 277.55,90 278.45,90 279.35,90 336,91.3 335.1,92.2 336,92.2 333.3,93.1 334.2,93.1 335.1,93.1 336,93.1 336.6,93.8 333.3,94 334.2,94 335.1,94 333.3,94.9 334.2,94.9 335.1,94.9 336,94.9 335.1,95.8 336,95.8 336,96.7 279.6,97.2 280.45,97.2 276.2,98.05 277.05,98.05 279.6,98.05 280.45,98.05 336.6,98.7 276.2,98.9 277.05,98.9 277.85,102.35 278.7,102.35 279.55,102.35 280.4,102.35 281.25,102.35 282.1,102.35 282.95,102.35 283.8,102.35 284.65,102.35 278.05,103.25 278.95,103.25 279.85,103.25 280.75,103.25 281.65,103.25 282.55,103.25 283.45,103.25 284.3,103.25 336.6,103.7 278.05,104.15 278.95,104.15 279.85,104.15 280.75,104.15 281.65,104.15 282.55,104.15 283.45,104.15 335.3,104.2 278.05,105.05 278.95,105.05 279.85,105.05 280.75,105.05 281.65,105.05 282.55,105.05 333.5,105.1 334.4,105.1 335.3,105.1 336.2,105.1 278.05,105.95 278.95,105.95 279.85,105.95 280.75,105.95 281.65,105.95 333.5,106 334.4,106 335.3,106 336.2,106 278.05,106.85 278.95,106.85 279.85,106.85 280.75,106.85 333.5,106.9 334.4,106.9 335.3,106.9 336.2,106.9 278.05,107.75 278.95,107.75 279.85,107.75 335.3,107.8 336.2,107.8 336.6,108.7 336.6,113.7 335.3,116.1 336.2,116.1 333.5,117 334.4,117 335.3,117 336.2,117 333.5,117.9 334.4,117.9 335.3,117.9 336.2,117.9 336.6,118.7 333.5,118.8 334.4,118.8 335.3,118.8 335.3,119.7 336.2,119.7 276.65,122.6 277.55,122.6 278.45,122.6 279.35,122.6 280.25,122.6 281.15,122.6 276.65,123.5 277.55,123.5 278.45,123.5 279.35,123.5 280.25,123.5 281.15,123.5 282.05,123.5 336.6,123.7 276.65,124.4 277.55,124.4 278.45,124.4 279.35,124.4 280.25,124.4 281.15,124.4 282.05,124.4 276.65,125.3 277.55,125.3 278.45,125.3 279.35,125.3 280.25,125.3 281.15,125.3 282.05,125.3 282.05,126.15 276.65,126.2 277.55,126.2 278.45,126.2 279.35,126.2 280.25,126.2 281.15,126.2 276.65,127.1 277.55,127.1 278.45,127.1 279.35,127.1 335.8,127.7 276.65,128 277.55,128 278.45,128 279.35,128 334.9,128.6 335.8,128.6 336.6,129.05 333.1,129.5 334,129.5 334.9,129.5 335.8,129.5 332.2,130.4 333.1,130.4 334,130.4 334.9,130.4 335.8,130.4 331.3,131.3 332.2,131.3 333.1,131.3 331.3,132.2 332.2,132.2 331.3,133.1 332.2,133.1 336.6,133.7 331.3,134 332.2,134 331.3,134.9 332.2,134.9 279.6,135.2 280.45,135.2 331.3,135.8 332.2,135.8 276.2,136.05 277.05,136.05 279.6,136.05 280.45,136.05 330.3,136.7 331.3,136.7 332.2,136.7 276.2,136.9 277.05,136.9 330.3,137.6 331.3,137.6 332.2,137.6 330.3,138.5 331.3,138.5 332.2,138.5 336.6,138.7 330.3,139.4 331.3,139.4 318.25,139.8 319.15,139.8 278.1,140.7 279,140.7 279.9,140.7 280.8,140.7 281.7,140.7 282.6,140.7 283.5,140.7 317.8,140.7 318.7,140.7 319.6,140.7 278.1,141.6 279,141.6 279.9,141.6 280.8,141.6 281.7,141.6 282.6,141.6 283.5,141.6 317.8,141.6 318.7,141.6 319.6,141.6 320.5,141.6 278.1,142.5 279,142.5 279.9,142.5 280.8,142.5 281.7,142.5 282.6,142.5 283.5,142.5 316.9,142.5 317.8,142.5 318.7,142.5 319.6,142.5 320.5,142.5 321.4,142.5 278.1,143.4 279,143.4 279.9,143.4 280.8,143.4 281.7,143.4 282.6,143.4 283.5,143.4 316,143.4 316.9,143.4 317.8,143.4 318.7,143.4 319.6,143.4 320.5,143.4 321.4,143.4 322.3,143.4 328.6,143.6 278.1,144.3 279,144.3 279.9,144.3 280.8,144.3 281.7,144.3 282.6,144.3 283.5,144.3 284.4,144.3 284.9,145.15 289.9,145.15 294.9,145.15 299.9,145.15 304.9,145.15 309.9,145.15 314.9,145.15 319.9,145.15 324.9,145.15 329.9,145.15 279,145.2 279.9,145.2 280.8,145.2 281.7,145.2 282.6,145.2 283.5,145.2
N03591: R116.2 R130.1 | length 1.3
  BOTTOM w0.7: R130.1@198.9,58.45 R116.2@198.9,59.8
N05004: Q5.G R28.2 R132.2 R133.2 | length 11.7
  TOP w0.6: 162.94,141.5 163.52,140.92 ; Q5.G@163.52,143.8 163.52,140.92 ; 164.1,141.5 163.52,140.92 ; R132.2@164.8,134.6 R133.2@164.8,136.9 R28.2@164.8,138.75 164.17,138.75 163.52,139.4 163.52,140.92
N07003: L6.1 T6.7 T6.8 T6.9 T6.13 TP17.1 | length 4.8
  BOTTOM w2.8: L6.1@287.975,103.75 L6.1@287.975,106.15 L6.1@287.975,108.55
N07083: C51.2 C69.2 D34.C D35.C R105.2 R106.2 R107.1 R129.2
N07119: C27.2 C68.2 D20.C D21.C R76.2 R77.2 R78.2 R128.1
N07203: Q11.4 Q12.4 R18.2 R19.2 R212.2 TP21.1 | length 21.1
  TOP w0.6: TP21.1@276.6,134.45 v1(277.75,134.45) ; Q11.4@276.9,145.18 v1(278.075,145.18)
  Mid-Layer 3 w0.6: v1(277.75,134.45) 278,134.7 278,137.8 277,138.8 v1(277,140.25) 277,144.48 277.7,145.18 v1(278.075,145.18)
  BOTTOM w0.5: R19.2@278.2,129.3 278.8,129.9 R18.2@278.8,131.1
  BOTTOM w0.6: v1(277,140.25) Q12.4@277,141.3 ; v1(277.75,134.45) 278.8,133.4 R212.2@278.8,133.3 R18.2@278.8,131.1
N07369: C104.2 D20.A Q13.5 Q13.6 Q13.7 Q13.8 Q14.5 Q14.6 Q14.7 Q14.8 T6.14 TP29.1
N07429: C107.2 D35.A Q7.5 Q7.6 Q7.7 Q7.8 Q8.5 Q8.6 Q8.7 Q8.8 T5.10 T5.11 T5.12
N11927: Q15.4 Q16.4 Q17.4 Q18.4 R6.2 TP28.1 | length 63
  TOP w0.6: TP28.1@308.75,41.75 v1(308.75,43.95)
  TOP w0.8: Q16.4@321.1,77.65 v1(321.1,78.95) ; Q15.4@327.6,77.65 v1(327.6,78.95)
  Mid-Layer 3 w0.3: v1(308.75,43.95) 313.65,48.85 313.65,54.75 311.7,56.7 v1(311.2,56.95)
  Mid-Layer 3 w0.8: v1(311.2,56.95) 309.8,58.35 309.8,75.6 313.15,78.95 v1(321.1,78.95) v1(327.6,78.95)
  BOTTOM w0.8: R6.2@311.2,56.05 v1(311.2,56.95) ; Q17.4@320.905,77.65 320.905,78.755 v1(321.1,78.95) ; Q18.4@327.405,77.65 327.405,78.755 v1(327.6,78.95)
N043041: D40.C R126.1 | length 2
  TOP w0.6: R126.1@181.65,95.3 D40.C@183.6,95.3
N043160: D41.A R127.1 | length 2.6
  TOP w0.6: R127.1@176.1,93.05 D41.A@178.7,93.05
N043261: D44.C R134.1 | length 1.6
  TOP w0.6: D44.C@194.3,90.5 R134.1@195.9,90.5
N043380: D45.A R135.1 | length 1.6
  TOP w0.6: D45.A@194.3,92.75 R135.1@195.9,92.75
N043481: D42.C R132.1 | length 1.6
  TOP w0.6: R132.1@168.05,134.6 D42.C@169.6,134.6
N043600: D43.A R133.1 | length 1.6
  TOP w0.6: R133.1@168,136.9 D43.A@169.6,136.9
N043701: D46.C R136.1 | length 1.6
  BOTTOM w0.6: R136.1@185.7,135 D46.C@187.3,135
N043820: D47.A R137.1 | length 1.6
  BOTTOM w0.6: R137.1@185.7,137.3 D47.A@187.3,137.3
N66342: D80.A Q80.D T8.3 TP80.1 | length 37.6
  TOP w0.5: TP80.1@201.307,41.81 204.38,41.81 206.92,44.35 Q80.D@208.65,44.35
  TOP w1: T8.3@229.77,44.5 T8.3@229.97,44.5
  TOP w1.68: TP80.1@200.1,41.81 TP80.1@201.307,41.81
  TOP w1.9: Q80.D@208.65,44.35 209.55,43.45
  TOP w2: 209.55,43.45 210.94,43.45 215.69,38.7 227.15,38.7 229.97,41.52 T8.3@229.97,44.5
N66362: Q80.S R803.1 R804.2 R812.2 R813.2 R814.2 | length 4.5
  BOTTOM w0.6: R803.1@208.6,53.4 R803.1@208.6,53.45 ; R804.2@208.6,54.55 R803.1@208.6,53.45 ; R813.2@211.95,53.45 R803.1@208.6,53.45
N14550647: C812.2 IC80.VS R808.1 R809.2 | length 5.4
  BOTTOM w0.4: R808.1@203.35,66.75 R809.2@204.6,66.75 ; IC80.VS@204.465,62.6 C812.2@204.465,65.6 ; C812.2@204.475,65.6 R809.2@204.475,66.75
N14553110: D90.A D91.A D92.A T8.12 T8.13 | length 30.8
  BOTTOM w2: 233.1,22 259,22 D90.A@262.45,25.45
N14557584: C800.2 C801.1 C807.1 F8.2 IC80.HV R800.2 T8.1 | length 84.3
  Mid-Layer 3 w0.3: v1(198.85,50.4) 198.85,46.2 205.41,39.64 209.11,39.64 211.15,37.6 C800.2@211.15,35.55
  BOTTOM w0.3: v1(198.85,50.4) 201.05,52.6 201.05,55.7 202.5,57.15 IC80.HV@203.002,57.15
  BOTTOM w0.59: IC80.HV@203.002,57.15 IC80.HV@203.2,57.15
  BOTTOM w1: F8.2@200.19,35 F8.2@200.45,35
  BOTTOM w2: F8.2@200.45,35.25 200.45,35.372 cw(c202.45,35.372) 201.036,36.786 203.564,39.314 cw(c204.978,37.9) 204.978,39.9 207.322,39.9 cw(c207.322,37.9) 208.736,39.314 211.395,36.655 ; C800.2@211.395,35.585 211.395,36.65 ; T8.1@237.39,44.5 237.39,50.59 R800.2@237.8,51 ; T8.1@237.4,44.5 237.4,42.1 231.95,36.65 211.4,36.65 ; 211.395,36.65 211.4,36.65 ; 211.395,36.65 211.395,36.655 ; 211.395,36.655 211.4,36.65
N14557651: D81.C R806.1 | length 1.4
  BOTTOM w0.6: R806.1@198.2,64.8 198.55,65.15 D81.C@198.55,66.1
N14557692: C802.2 IC80.VDD R806.2 | length 3.6
  BOTTOM w0.6: R806.2@201.4,64.35 C802.2@201.4,62.6 IC80.VDD@203.2,62.6
N14557973: IC80.NTC R807.2 | length 1.9
  BOTTOM w0.4: IC80.NTC@205.735,62.6 R807.2@205.735,64.45
N14565222: IC80.DRV R802.1 | length 2.2
  BOTTOM w0.6: IC80.DRV@205.735,57.2 205.735,56.065 R802.1@206.5,55.3
N14565783: C803.2 IC80.CS R804.1 | length 2.7
  BOTTOM w0.6: IC80.CS@207.005,57.2 C803.2@208.6,57.2 ; R804.1@208.6,56 C803.2@208.6,57.15
N14565980: D82.A T8.5 | length 6.2
  TOP w1.5: T8.5@220.92,44.5 220.92,49.97 v1(221.45,50.5)
  other v1: 222.35,50.5 221.45,51.4 222.35,51.4
N16776505: Q80.G R802.2 R803.2 | length 4.8
  BOTTOM w0.6: Q80.G@206.11,49.35 206.5,50.5 R802.2@206.5,51.95 ; R802.2@206.5,52 R803.2@208.6,52
N16785059: C801.2 C807.2 D80.C R800.1
N16790081: C810.1 R801.1
N16975142: T6.3 T6.4 | length 20.3
  TOP w6.1: T6.4@223.72,122.42 T6.3@223.72,132.58
  BOTTOM w6.1: T6.4@223.72,122.42 T6.3@223.72,132.58
N16985418: T5.3 T5.4 | length 20.3
  TOP w6.1: T5.4@223.72,83.82 T5.3@223.72,93.98
  BOTTOM w6.1: T5.4@223.72,83.82 T5.3@223.72,93.98
N17045135: C104.1 R118.2
N17045143: C107.1 R141.2
N17045153: C106.1 R140.2
N17045822: C105.1 R119.2
OUTA1: IC21.4 R111.1 R187.2 | length 154
  TOP w0.6: v1(163.6,129.7) 163.8,129.5 R111.1@164.5,129.5
  Mid-Layer 2 w0.3: v1(163.6,129.7) 164.45,129.7 165.45,128.7 165.45,115.634 161.35,111.534 161.35,98 174.95,84.4 192.799,84.4 217.699,59.5 218.449,59.5 220.7,57.249 220.7,49.399 223.575,46.524 223.575,43.875 227.55,39.9 243.399,39.9 244.199,39.1 v1(244.7,39.1)
  BOTTOM w0.3: v1(244.7,39.1) 244.7,38.75 245.1,38.35 246.361,38.35 R187.2@247,38.6
  BOTTOM w0.4: R187.2@247,38.6 247,39.4 247.1,39.5 IC21.4@247.1,40.15
OUTA2: IC10.22 R149.2 | length 10
  BOTTOM w0.3: R149.2@267.2,42.55 267.95,42.55 269.875,40.625 IC10.22@275.683,40.625
  BOTTOM w0.4: IC10.22@275.683,40.625 IC10.22@276.437,40.625
OUTB1: IC22.4 R110.1 R189.2 | length 154.2
  TOP w0.6: v1(163.6,126.3) 163.8,126.1 R110.1@164.5,126.1
  Mid-Layer 2 w0.3: v1(163.6,126.3) 164.4,126.3 164.85,125.85 164.85,115.883 160.75,111.783 160.75,97.751 174.701,83.8 192.55,83.8 217.45,58.9 218.2,58.9 220.1,57 220.1,49.15 223.075,46.175 223.075,43.526 227.301,39.3 243.15,39.3 243.65,38.8 243.65,36.1 v1(244.7,35.05)
  BOTTOM w0.3: v1(244.7,35.05) 244.7,34.65 245,34.35 246.35,34.35 246.488,34.382 R189.2@247,34.5
  BOTTOM w0.4: R189.2@247,34.5 247,35.85 IC22.4@247.15,35.85
OUTB2: IC10.21 R150.2 | length 10.4
  BOTTOM w0.3: R150.2@267.417,37.8 268.2,37.8 268.502,38.102 268.502,38.602 269.875,39.975 IC10.21@275.683,39.975
  BOTTOM w0.4: IC10.21@275.683,39.975 IC10.21@276.437,39.975
  BOTTOM w0.7: R150.2@267.2,37.8 R150.2@267.417,37.8
OUTC1: IC23.4 R113.1 R191.2 | length 95.5
  TOP w0.3: R113.1@181.8,81.3 182.6,80.5 183.95,80.5 185.15,81.7 188.825,81.7 v1(189.375,82.25) ; v1(242.9,38.55) 242.9,40.4 245.2,42.7 R191.2@247.05,42.7
  TOP w0.4: IC23.4@247.05,41.25 247.05,41.85 247.25,42.05 R191.2@247.25,42.7
  TOP w0.6: R191.2@247.05,42.7 R191.2@247.25,42.7
  Mid-Layer 2 w0.2: v1(189.375,82.25) 189.375,81.525 190.1,80.8 194.5,80.8 217.15,58.15 217.866,58.15 219.35,56.666 219.35,48.816 222.625,45.541 222.625,42.875 226.95,38.55 v1(242.9,38.55)
OUTC2: IC10.20 R151.2 | length 13.9
  TOP w0.3: R151.2@267.325,40 268.25,40 268.6,39.65 v1@277.9,39.65 ; v1@277.9,39.65 v1(278.1,39.85) v1@277.9,39.65
  TOP w0.7: R151.2@267.2,40 R151.2@267.325,40
  BOTTOM w0.3: IC10.20@276.95,39.325 277.5,39.325 277.773,39.598 v1(278.1,39.85)
  BOTTOM w0.4: IC10.20@276.95,39.325 276.437,39.325 IC10.20@277.03,39.325
OUTD1: IC24.4 R112.1 R193.2 | length 93.1
  TOP w0.3: R112.1@183.2,81.325 183.85,81.325 184.825,82.3 188.05,82.3 v1(188.85,83.1) ; v1(242.9,37.3) 243.95,38.35 246.25,38.35 246.4,38.5 R193.2@247.083,38.5
  TOP w0.4: IC24.4@247.05,37.05 247.05,37.5 247.295,37.745 R193.2@247.295,38.5
  TOP w0.7: R193.2@247.083,38.5 R193.2@247.3,38.5
  Mid-Layer 2 w0.2: v1(188.85,83.1) 188.716,82.65 188.716,81.584 189.9,80.4 194.334,80.4 216.984,57.75 217.7,57.75 218.95,56.5 218.95,48.65 222.225,45.375 222.225,42.709 226.784,38.15 242.05,38.15 v1(242.9,37.3)
OUTD2: IC10.19 R152.2 | length 16.4
  TOP w0.3: R152.2@267.375,35.2 267.9,35.2 268.3,35.6 268.3,38.5 268.65,38.85 v1(278.1,38.85)
  TOP w0.7: R152.2@267.2,35.2 R152.2@267.375,35.2
  BOTTOM w0.3: IC10.19@277.038,38.675 277.726,38.675 v1(278.1,38.85)
  BOTTOM w0.4: IC10.19@277.038,38.675 276.437,38.675 IC10.19@277.065,38.675
OUTE: IC6.2 IC7.2 IC10.18 TP25.1 | length 106.2
  TOP w0.2: IC7.2@283.04,79.45 283.65,79.45 283.9,79.7 283.9,82.4 284.85,83.35 TP25.1@289.8,83.35
  TOP w0.3: v1(280.95,78.6) 281.077,78.992 281.366,79.281 IC7.2@281.95,79.45 ; v1(280.95,116.7) 281.077,117.092 281.366,117.381 IC6.2@281.95,117.55
  TOP w0.57: IC7.2@282.55,79.45 IC7.2@283.04,79.45
  TOP w1.7: TP25.1@289.8,83.35 TP25.1@290.95,83.35
  Mid-Layer 3 w0.3: v1(280.95,78.6) 280.2,79.35 276,79.35 273.6,81.75 273.6,107.767 280.95,115.117 v1(280.95,116.7)
  Mid-Layer 3 w0.4: v1(278.1,37.85) 277.75,38.05 277.25,38.55 277.25,40.9 277.9,41.55 277.9,62.076 280.6,64.776 280.6,77.8 280.95,78.15 v1(280.95,78.6)
  BOTTOM w0.3: IC10.18@277.038,38.025 277.726,38.025 v1(278.1,37.85)
  BOTTOM w0.4: IC10.18@277.038,38.025 276.437,38.025 IC10.18@277.115,38.025
OUTF: IC6.4 IC7.4 IC10.17 TP24.1 | length 109.2
  TOP w0.3: v1(279.9,78.55) 279.9,81.2 280.7,82 IC7.4@281.822,82 ; v1(279.9,117.4) 279.9,119.3 280.7,120.1 IC6.4@281.822,120.1 ; IC6.4@283.04,120.105 284.005,120.105 285.25,121.35 TP24.1@285.25,122.6
  TOP w0.59: IC7.4@281.822,82 IC7.4@282.5,82 ; IC6.4@281.822,120.1 IC6.4@282.5,120.1
  TOP w0.6: IC6.4@282.5,120.105 IC6.4@283.04,120.105
  TOP w1.7: TP24.1@285.25,122.6 TP24.1@285.25,123.35
  Mid-Layer 3 w0.3: v1(279.9,78.55) 279.55,78.75 275.751,78.75 273,81.501 273,108.016 279.9,114.916 v1(279.9,117.4)
  Mid-Layer 3 w0.4: v1(278.1,36.6) 276.55,38.15 276.55,41.19 277.2,41.84 277.2,62.366 279.9,65.066 v1(279.9,78.55)
  BOTTOM w0.3: IC10.17@276.95,37.375 277.5,37.375 277.909,36.966 v1(278.1,36.6)
  BOTTOM w0.4: IC10.17@276.95,37.375 276.437,37.375 IC10.17@277.03,37.375
P48V: C92.2 C93.2 C100.2 CN6.1 CN6.2 IC8.4 Q15.5 Q15.6 Q15.7 Q15.8 Q16.5 Q16.6 Q16.7 Q16.8 Q17.5 Q17.6 Q17.7 Q17.8 Q18.5 Q18.6 Q18.7 Q18.8 | length 12
  BOTTOM w0.6: C100.2@308.55,53.1 IC8.4@310.3,53.1
  BOTTOM w1: C100.2@308.55,53.25 308.55,56.55 310.25,58.25 314.75,58.25
  other v1: 321.55,66.4 322.75,66.4 323.95,66.4 325.15,66.4 326.35,66.4 327.55,66.4 328.75,66.4 329.95,66.4 320.95,67 322.15,67 323.35,67 324.55,67 325.75,67 326.95,67 328.15,67 329.35,67 321.55,67.6 322.75,67.6 323.95,67.6 325.15,67.6 326.35,67.6 327.55,67.6 328.75,67.6 329.95,67.6 320.95,68.2 322.15,68.2 323.35,68.2 324.55,68.2 325.75,68.2 326.95,68.2 328.15,68.2 329.35,68.2 321.55,68.8 322.75,68.8 323.95,68.8 325.15,68.8 326.35,68.8 327.55,68.8 328.75,68.8 329.95,68.8 320.95,69.4 322.15,69.4 323.35,69.4 324.55,69.4 325.75,69.4 326.95,69.4 328.15,69.4 329.35,69.4 321.55,70 322.75,70 323.95,70 325.15,70 326.35,70 327.55,70 328.75,70 329.95,70 320.95,70.6 322.15,70.6 323.35,70.6 324.55,70.6 325.75,70.6 326.95,70.6 328.15,70.6 329.35,70.6
PFC_OUT: C1.2 C7.2 D1.C D2.C D3.1 F8.1 R92.2 R178.2 T4.2 TP44.1 | length 427.2
  TOP w0.3: TP44.1@180.95,23.572 v1(180.95,25.25)
  TOP w1.7: TP44.1@180.95,22.4 TP44.1@180.95,23.572
  TOP w3.5: C1.2@177.7,49.4 182.336,54.036 ccw(c178.8,57.571) 183.8,57.571 183.8,58.179 cw(c188.8,58.179) 185.264,61.714 195.036,71.486 cw(c198.571,67.95) 198.571,72.95 206.489,72.95 cw(c206.489,67.95) 210.024,71.486 215.867,65.643 ccw(c223.575,73.35) 223.575,62.45 233.979,62.45 cw(c233.979,57.45) 237.514,60.986 243.646,54.854 ; 243.646,54.854 cw(c240.11,51.319) 245.11,51.319 T4.2@245.11,48.75
  BOTTOM w0.3: R92.2@178.55,32.2 178.55,31.45 180.95,29.05 v1(180.95,25.25) ; R92.2@178.8,32.25 179.7,32.25 183.7,36.25 183.7,43.95 185.2,45.45 185.2,45.95 ; 184.75,46.4 185.2,45.95 ; 185.2,47.9 185.2,47.15 185.2,45.95 ; 185.65,46.4 185.2,45.95
  BOTTOM w0.6: R92.2@178.6,32.25 R92.2@178.8,32.25
  BOTTOM w2: C7.2@145.6,49.4 C7.2@145.6,49.65 ; 185.2,47.15 191.85,47.15 194.85,44.15 F8.1@194.85,35.65
  BOTTOM w3: D1.C@155.18,76.7 D1.C@155.18,76.31 155.18,68.87 156.2,67.85 156.2,50.7 ; 181.5,54.05 181.5,67.515 186.38,72.395 D2.C@186.38,76.31 D2.C@186.38,76.7
  BOTTOM w3.5: C1.2@177.7,49.4 183.7,49.4 ; 185.2,47.9 183.7,49.4 ; T4.2@245.11,48.75 245.11,51.319 ccw(c240.11,51.319) 243.646,54.854 237.514,60.986 ccw(c233.979,57.45) 233.979,62.45 223.575,62.45 cw(c223.575,73.35) 215.867,65.643 210.024,71.486 ccw(c206.489,67.95) 206.489,72.95 198.571,72.95 ccw(c198.571,67.95) 195.036,71.486 187.164,63.614 ccw(c190.7,60.079) 185.7,60.079 185.7,49.4 183.7,49.4
  BOTTOM w7: 120.95,137.4 120.95,131 118.45,128.5 118.45,98.4 122.5,94.35 122.5,68.65 141.45,49.7 C7.2@145.6,49.7 ; C7.2@145.55,49.65 145.6,49.65 155.25,49.65 157.3,47.6 170.45,47.6 172.5,49.65 C1.2@177.9,49.65
PFC_VIN: D8.C D9.C R95.2 | length 16.2
  TOP w0.5: 144.575,139.05 143.925,138.4 144.575,139.05 ; 144.575,139.05 v1(145.05,139.05) ; 144.575,139.05 v1(145.05,139.05) ; v1(145.05,139.05) v1(146.3,139.05) v1(145.05,139.05)
  TOP w1: D8.C@143.925,134.9 143.925,138.4 D8.C@143.925,134.9
  BOTTOM w0.5: R95.2@143.9,138.34 144.61,139.05 v1(145.05,139.05) ; v1(145.05,139.05) v1(146.3,139.05) v1(145.05,139.05)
